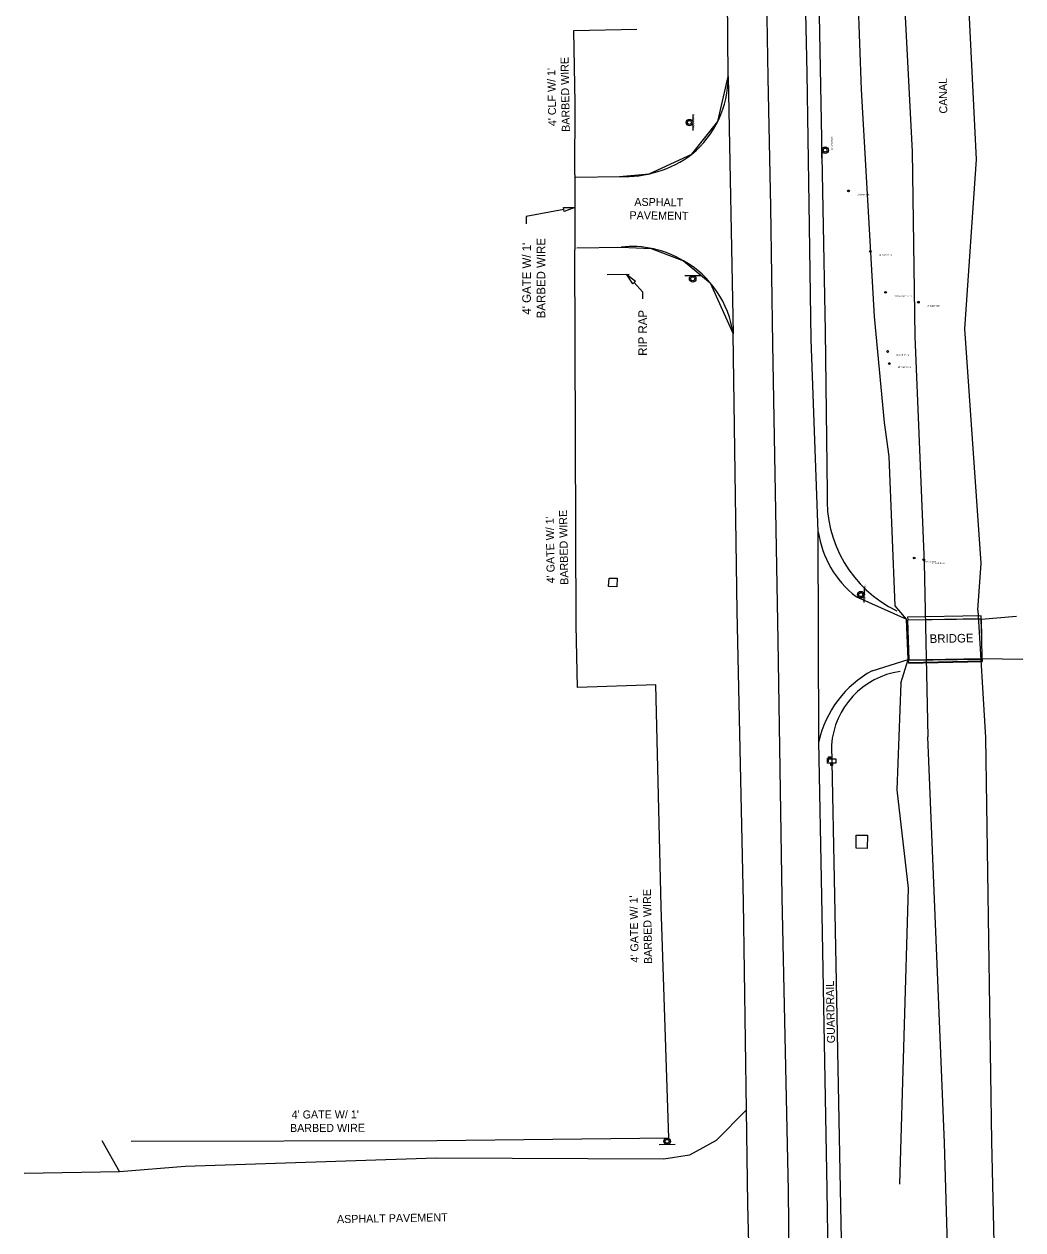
# Model space of a CAD drawing. Extents: x 925226 to 926411, y 852913 to 858733.
# Drawn here: x 925566 to 925915.3, y 853988.5 to 854410.4 of the extents above; entities that cross this region are included whole.
import ezdxf

# ---------------------------------------------------------------- set-up
doc = ezdxf.new("R2010")
doc.units = 0
for name, color, linetype in [('BankMent_ep', 7, 'Continuous'), ('Bridge_ep', 7, 'Continuous'), ('BridgeEle_ep', 7, 'Continuous'), ('CLConst_dp', 7, 'Continuous'), ('ConcSlabs_ep', 7, 'Continuous'), ('CurveData_dp', 7, 'Continuous'), ('Fence_ep', 7, 'Continuous'), ('Gates_ep', 7, 'Continuous'), ('InletCurb_ep', 7, 'Continuous'), ('InletDBI_ep', 7, 'Continuous'), ('ManholeSW_ep', 7, 'Continuous'), ('PavtAsphalt_ep', 7, 'Continuous'), ('PavtConcrete_ep', 7, 'Continuous'), ('PavtCrown_ep', 7, 'Continuous'), ('PavtMisc_ep', 7, 'Continuous'), ('RipRap_ep', 7, 'Continuous'), ('TextLabel', 7, 'Continuous'), ('WaterEdge_ep', 7, 'Continuous')]:
    doc.layers.add(name, color=color, linetype=linetype)

# ---------------------------------------------------------------- blocks, each defined once
blk = doc.blocks.new('SSS')
at = {"layer": 'ManholeSW_ep'}
blk.add_line((-2.77, 1.15), (2.77, 1.15), dxfattribs=at)
for radius in [1.15, 0.692]:
    blk.add_circle((0, 0), radius, dxfattribs=at)
blk = doc.blocks.new('MBX')
at = {"layer": 'InletCurb_ep'}
for points in [[(-1.5, 1.42), (-1.5, 1.45), (1.5, 1.45), (1.5, 0), (-1.5, 0), (-1.5, 1.42), (-1.53, 1.55), (-1.59, 1.55)], [(-1.15, 0.38), (-1.15, 2.22), (-0.33, 2.22), (-0.33, 1.7), (-1.15, 1.7)], [(0.26, 0), (0.26, -0.82), (-0.26, -0.82), (-0.26, 0)]]:
    blk.add_lwpolyline(points, dxfattribs=at)
blk = doc.blocks.new('TREEPA')
at = {"layer": 'InletDBI_ep'}
blk.add_circle((0, 0), 0.3, dxfattribs=at)

msp = doc.modelspace()

# ---------------------------------------------------------------- linework, layer by layer
at = {"layer": 'BankMent_ep'}
for p, q in [((925858.91, 854387.53), (925855.92, 854470.06)), ((925863.41, 854308.04), (925858.91, 854387.53)), ((925866.95, 854270.98), (925863.41, 854308.04)), ((925868.63, 854259.1), (925866.95, 854270.98)), ((925870.66, 854206.81), (925868.63, 854259.1)), ((925872.64, 854179.79), (925875.22, 854188.09)), ((925872.64, 854179.79), (925871.26, 854142.38)), ((925871.26, 854142.38), (925875.17, 854107.98)), ((925875.17, 854107.98), (925872.17, 854004.47))]:
    msp.add_line(p, q, dxfattribs=at)
at = {"layer": 'Bridge_ep'}
for p, q in [((925874.99, 854202.87), (925874.98, 854202.83)), ((925874.98, 854202.83), (925875.05, 854201.87)), ((925900.72, 854203.37), (925874.99, 854202.87)), ((925900.78, 854202.2), (925875.03, 854201.81)), ((925875.03, 854201.81), (925875.42, 854187.92)), ((925875.05, 854201.87), (925900.71, 854202.36)), ((925900.71, 854202.36), (925900.72, 854203.18)), ((925900.72, 854203.18), (925900.72, 854203.37)), ((925900.93, 854195.36), (925900.78, 854202.2)), ((925901.04, 854188.35), (925900.93, 854195.36)), ((925875.42, 854187.92), (925901.04, 854188.35))]:
    msp.add_line(p, q, dxfattribs=at)
at = {"layer": 'BridgeEle_ep'}
for p, q in [((925875.34, 854187.8), (925901.08, 854188.18)), ((925875.34, 854187.8), (925875.42, 854187.92)), ((925875.42, 854186.91), (925875.34, 854187.8)), ((925875.38, 854186.72), (925901.2, 854187.32)), ((925875.42, 854186.91), (925875.38, 854186.72)), ((925901.11, 854187.44), (925875.42, 854186.91)), ((925901.08, 854188.18), (925901.04, 854188.35)), ((925901.08, 854188.18), (925901.11, 854187.44)), ((925901.2, 854187.32), (925901.11, 854187.44))]:
    msp.add_line(p, q, dxfattribs=at)
at = {"layer": 'ConcSlabs_ep'}
for p, q in [((925770.39, 854213.55), (925770.59, 854216.44)), ((925770.59, 854216.44), (925773.39, 854216.45)), ((925773.39, 854216.45), (925773.38, 854213.48)), ((925773.38, 854213.48), (925770.39, 854213.55)), ((925857.04, 854122.08), (925857.05, 854126.6)), ((925857.05, 854126.6), (925860.97, 854126.58)), ((925860.97, 854126.58), (925860.87, 854121.94)), ((925860.87, 854121.94), (925857.04, 854122.08))]:
    msp.add_line(p, q, dxfattribs=at)
at = {"layer": 'CurveData_dp'}
for p, q in [((925843.12, 854468.11), (925844.59, 854388.81)), ((925844.59, 854388.81), (925846.22, 854302.95)), ((925846.22, 854302.95), (925846.91, 854246.34)), ((925848.38, 854158.03), (925849.43, 854105.39)), ((925849.43, 854105.39), (925851.39, 854002.8)), ((925851.39, 854002.8), (925852.81, 853933.11))]:
    msp.add_line(p, q, dxfattribs=at)
for centre, major_axis, ratio, start_param, end_param in [((925890.07, 854243.99), (-7.31, 42.66), 0.99859, 1.347213, 2.519855), ((925876.63, 854155.82), (4.11, 28.1), 0.997811, 0.29556, 1.638287)]:
    msp.add_ellipse(centre, major_axis=major_axis, ratio=ratio, start_param=start_param, end_param=end_param, dxfattribs=at)
at = {"layer": 'Fence_ep'}
for p, q in [((925758.31, 854408.11), (925780.35, 854408.53)), ((925758.72, 854382.66), (925758.31, 854408.11)), ((925758.69, 854357.64), (925758.72, 854382.66)), ((925759.09, 854200), (925758.65, 854331.39)), ((925759.63, 854178.23), (925759.09, 854200)), ((925786.95, 854179.12), (925759.63, 854178.23)), ((925788.84, 854101.65), (925786.95, 854179.12)), ((925791.54, 854020.54), (925788.84, 854101.65)), ((925791.54, 854020.54), (925710.43, 854019.63)), ((925710.43, 854019.63), (925603.51, 854019.35))]:
    msp.add_line(p, q, dxfattribs=at)
at = {"layer": 'Gates_ep'}
msp.add_line((925758.69, 854357.64), (925758.65, 854331.39), dxfattribs=at)
at = {"layer": 'PavtAsphalt_ep'}
for p, q in [((925812.27, 854391.97), (925811.7, 854469.29)), ((925839.94, 854393.15), (925838.3, 854468.8)), ((925812.27, 854391.97), (925814.03, 854301.97)), ((925840.55, 854347.45), (925839.94, 854393.15)), ((925841.26, 854300), (925840.55, 854347.45)), ((925815.39, 854204.82), (925814.03, 854301.97)), ((925843.79, 854232.75), (925841.26, 854300)), ((925843.97, 854159.33), (925843.79, 854232.75)), ((925817.58, 854103.22), (925815.39, 854204.82)), ((925845, 854105.18), (925843.97, 854159.33)), ((925846.94, 854002.63), (925845, 854105.18)), ((925818.72, 854030.5), (925817.58, 854103.22)), ((925819.15, 853997.45), (925818.72, 854030.5)), ((925847.73, 853940.75), (925846.94, 854002.63)), ((925819.85, 853968.35), (925819.15, 853997.45))]:
    msp.add_line(p, q, dxfattribs=at)
at = {"layer": 'PavtConcrete_ep'}
for p, q in [((925808.61, 854376.24), (925812.27, 854391.97)), ((925799.58, 854364.84), (925808.61, 854376.24)), ((925784.65, 854357.96), (925799.58, 854364.84)), ((925774.3, 854357.05), (925784.65, 854357.96)), ((925758.98, 854356.85), (925774.3, 854357.05)), ((925758.98, 854356.85), (925774.3, 854357.05)), ((925759.38, 854332.13), (925774.8, 854332.35)), ((925759.38, 854332.13), (925774.8, 854332.35)), ((925774.8, 854332.35), (925785.36, 854331.88)), ((925785.36, 854331.88), (925796.65, 854327.57)), ((925796.65, 854327.57), (925806.02, 854319.82)), ((925806.02, 854319.82), (925814.03, 854301.97)), ((925593.16, 854019.71), (925599.4, 854008.77)), ((925599.4, 854008.77), (925566.04, 854008.18))]:
    msp.add_line(p, q, dxfattribs=at)
for centre, major_axis, ratio, start_param, end_param in [((925777.24, 854391.83), (-5.39, 34.62), 0.999796, 3.678582, 4.56208), ((925776.1, 854396.09), (-38.89, -4.25), 0.998997, 1.41617, 2.105942), ((925778.52, 854297.02), (-35.33, -3.83), 0.999762, 4.06904, 4.709356), ((925779.36, 854297.14), (-25.25, -24.24), 0.999952, 2.514878, 3.430744)]:
    msp.add_ellipse(centre, major_axis=major_axis, ratio=ratio, start_param=start_param, end_param=end_param, dxfattribs=at)
at = {"layer": 'PavtCrown_ep'}
for p, q in [((925824.85, 854469.49), (925826.14, 854391.69)), ((925826.14, 854391.69), (925827.04, 854346.43)), ((925827.04, 854346.43), (925827.81, 854298.37)), ((925827.81, 854298.37), (925829.67, 854194.74)), ((925829.67, 854194.74), (925831.05, 854104.93)), ((925831.05, 854104.93), (925833.25, 854002.14)), ((925833.25, 854002.14), (925834.7, 853885.26))]:
    msp.add_line(p, q, dxfattribs=at)
at = {"layer": 'PavtMisc_ep'}
for p, q in [((925856.97, 854210.1), (925874.66, 854202.14)), ((925875.22, 854188.09), (925874.66, 854202.14)), ((925900.78, 854202.2), (925913.05, 854203.2)), ((925901.04, 854188.35), (925900.83, 854202.25)), ((925862.68, 854184.1), (925875.22, 854188.09)), ((925901.04, 854188.35), (925915.33, 854188.19)), ((925818.72, 854030.5), (925808.09, 854019.79)), ((925808.09, 854019.79), (925798.73, 854014.57)), ((925710.18, 854013.52), (925622.31, 854010.64)), ((925789.82, 854013.19), (925710.18, 854013.52)), ((925798.73, 854014.57), (925789.82, 854013.19)), ((925622.31, 854010.64), (925599.4, 854008.77))]:
    msp.add_line(p, q, dxfattribs=at)
for centre, major_axis, ratio, start_param, end_param in [((925878.27, 854237.62), (28.89, -19.47), 0.999004, 3.875568, 4.647025), ((925880.43, 854151.24), (32.44, -18.5), 0.999665, 2.584277, 3.441629)]:
    msp.add_ellipse(centre, major_axis=major_axis, ratio=ratio, start_param=start_param, end_param=end_param, dxfattribs=at)
at = {"layer": 'RipRap_ep'}
msp.add_line((925769.9, 854322.75), (925777.6, 854322.85), dxfattribs=at)
at = {"layer": 'TextLabel'}
for points in [[(925754.74, 854345.5), (925741.66, 854343.05)], [(925741.66, 854343.05), (925741.66, 854340.51)], [(925779.4, 854319.91), (925782.35, 854316.74)], [(925782.35, 854316.74), (925782.35, 854314.21)]]:
    msp.add_lwpolyline(points, dxfattribs=at)
for points in [[(925754.62, 854346.15), (925758.67, 854346.23), (925754.87, 854344.84)], [(925778.91, 854319.46), (925776.67, 854322.84), (925779.89, 854320.36)]]:
    msp.add_lwpolyline(points, close=True, dxfattribs=at)
at = {"layer": 'WaterEdge_ep'}
for p, q in [((925872.52, 854445.23), (925876.6, 854365.74)), ((925899.17, 854363), (925895.07, 854443.45)), ((925876.6, 854365.74), (925877.53, 854301.09)), ((925895.08, 854303.79), (925899.17, 854363)), ((925900.73, 854221.79), (925895.08, 854303.79)), ((925877.53, 854301.09), (925880.81, 854221.89)), ((925880.81, 854221.89), (925882.06, 854161.01)), ((925899.59, 854205.28), (925900.73, 854221.79)), ((925874.66, 854202.14), (925870.66, 854206.81)), ((925899.59, 854205.28), (925902.23, 854160.76)), ((925887.87, 854018.96), (925882.06, 854161.01)), ((925902.23, 854160.76), (925904.38, 854019.34)), ((925890.48, 853931.53), (925887.87, 854018.96)), ((925904.38, 854019.34), (925906.39, 853930.37))]:
    msp.add_line(p, q, dxfattribs=at)

# ---------------------------------------------------------------- block references
at = {"layer": 'InletCurb_ep'}
msp.add_blockref('MBX', (925848.46, 854151.8), dxfattribs=at)
at = {"layer": 'InletDBI_ep'}
for p in [(925854.35, 854351.99), (925861.98, 854330.81), (925867.3, 854316.49), (925878.81, 854313.04), (925868.04, 854295.81), (925868.62, 854291.59), (925877.33, 854223.54), (925880.67, 854222.92)]:
    msp.add_blockref('TREEPA', p, dxfattribs=at)
at = {"layer": 'ManholeSW_ep'}
for p, rotation in [((925798.73, 854375.94), -90.00000000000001), ((925846.19, 854366.26), 89.99999999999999), ((925858.65, 854210.72), -90.84834561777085), ((925790.92, 854019.44), -179.36563587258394)]:
    msp.add_blockref('SSS', p, dxfattribs=dict(at, rotation=rotation))
msp.add_blockref('SSS', (925799.86, 854321.25), dxfattribs=at)

# ---------------------------------------------------------------- texts
at = {"layer": 'CLConst_dp'}
for s, rotation, p in [('NO STOPPING', 90, (925800.4, 854374.11)), ('NO STOPPING', 90, (925848.86, 854366.26)), ('SSS STOP SIGN', 89.1517, (925860.34, 854208.96))]:
    msp.add_text(s, height=0.5, rotation=rotation, dxfattribs=at).set_placement(p)
for s, p in [('18"CAB PALM', (925857.35, 854350.47)), ('18"CAB PALM', (925864.98, 854329.29)), ('18"CAB PALM 24"SF', (925870.3, 854314.97)), ('18"CAB PALM', (925881.81, 854311.53)), ('15"CAB PALM', (925871.04, 854294.29)), ('15"CAB PALM', (925871.62, 854290.08)), ('18"CAB PALM', (925880.33, 854222.02)), ('15"CAB PALM', (925883.67, 854221.4))]:
    msp.add_text(s, height=0.5, dxfattribs=at).set_placement(p)
at = {"layer": 'TextLabel'}
for s, height, rotation, p in [('BARBED WIRE', 2.8, 91.0261, (925756.9, 854372.68)), ("4' CLF W/ 1' ", 2.8, 91.0261, (925752.15, 854374.69)), ('CANAL', 2.8, 90.9639, (925888.92, 854379.08)), ('ASPHALT ', 2.8, 359.3465, (925779.44, 854346.77)), ('PAVEMENT', 2.8, 359.3465, (925777.76, 854342.09)), ("4' GATE W/ 1'", 3, 90, (925743.26, 854308.7)), ('BARBED WIRE', 3, 90, (925748.29, 854307.42)), ('RIP RAP', 3, 90, (925783.85, 854294.29)), ('BARBED WIRE', 2.8, 91.0261, (925756.37, 854214.21)), ("4' GATE W/ 1' ", 2.8, 91.0261, (925751.64, 854214.71)), ('BRIDGE', 3, 0.9741, (925882.73, 854193.8)), ("4' GATE W/ 1' ", 2.8, 91.0261, (925780.96, 854082.03)), ('BARBED WIRE', 2.8, 91.0261, (925785.69, 854081.53)), ('GUARDRAIL', 2.8, 91.0933, (925849.64, 854053.8)), ("4' GATE W/ 1' ", 2.8, 0.1543, (925659.61, 854027.43)), ('BARBED WIRE', 2.8, 0.1543, (925659.03, 854022.71)), ('ASPHALT PAVEMENT', 2.8, 1.0261, (925675.49, 853990.81))]:
    msp.add_text(s, height=height, rotation=rotation, dxfattribs=at).set_placement(p)

doc.saveas('drawing.dxf')
